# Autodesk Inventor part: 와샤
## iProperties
IsCustomPart: 0
Created: 2009-02
Part Number: 와샤
Material: 강, 연강
Description: 평면 와셔
Document SubType Name: Modeling
Standard: KS B 1326
Designer: 한국산업디자인학원
Standards Organization: KS
Language: ko-KR
Size Designation: 5x10
Categories: <MemberInstance><Categories><Category DisplayName="조임쇠" InternalName="e4da775c-781d-43d5-af7c-5136215cf5a6" Mnemonic="FSTN"><Category DisplayName="와셔" InternalN
Density: 1 g/cm^3
Author: 한국산업디자인학원
